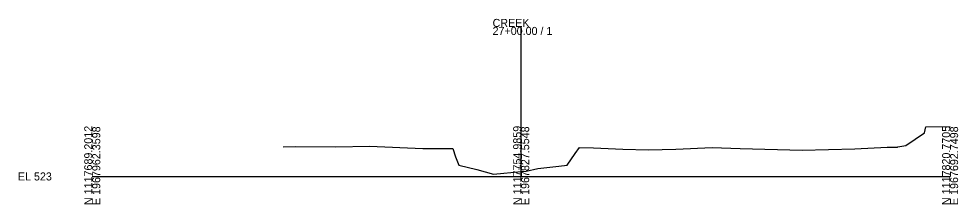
# Model space of a CAD drawing. Extents: x 9974 to 10303, y 9990 to 19550.
# Drawn here: x 9974.3 to 10302.8, y 16990.3 to 17055.1 of the extents above; entities that cross this region are included whole.
import ezdxf

# ---------------------------------------------------------------- set-up
doc = ezdxf.new("R2010")
doc.units = 0
for name, color, linetype in [('Level 10', 7, 'Continuous'), ('Level 60', 7, 'Continuous'), ('Level 63', 7, 'Continuous')]:
    doc.layers.add(name, color=color, linetype=linetype)

msp = doc.modelspace()

# ---------------------------------------------------------------- linework, layer by layer
at = {"layer": 'Level 60'}
for p, q in [((10284.54, 17010.84), (10291, 17015.18)), ((10291, 17015.18), (10291.56, 17017.33)), ((10291.56, 17017.33), (10299.98, 17017.41)), ((10299.98, 17017.41), (10300, 17017.41)), ((10066.8, 17010.4), (10071.23, 17010.43)), ((10071.23, 17010.43), (10085.16, 17010.39)), ((10085.16, 17010.39), (10097.01, 17010.6)), ((10097.01, 17010.6), (10115.59, 17009.72)), ((10115.59, 17009.72), (10126.08, 17009.73)), ((10126.08, 17009.73), (10127.07, 17006.86)), ((10168.84, 17007.98), (10170.4, 17010.15)), ((10170.4, 17010.15), (10175.27, 17009.97)), ((10175.27, 17009.97), (10185.52, 17009.58)), ((10185.52, 17009.58), (10194.51, 17009.27)), ((10194.51, 17009.27), (10204.12, 17009.58)), ((10204.12, 17009.58), (10216.77, 17010.13)), ((10216.77, 17010.13), (10226.55, 17009.75)), ((10226.55, 17009.75), (10248.22, 17009.19)), ((10248.22, 17009.19), (10266.69, 17009.59)), ((10266.69, 17009.59), (10277.98, 17010.28)), ((10277.98, 17010.28), (10280.03, 17010.23)), ((10280.03, 17010.23), (10281.63, 17010.22)), ((10281.63, 17010.22), (10281.69, 17010.38)), ((10281.69, 17010.38), (10284.54, 17010.84)), ((10127.07, 17006.86), (10128.19, 17003.9)), ((10166.09, 17003.99), (10168.84, 17007.98)), ((10128.19, 17003.9), (10134.48, 17002.37)), ((10134.48, 17002.37), (10140.32, 17000.77)), ((10140.32, 17000.77), (10150, 17001.72)), ((10150, 17001.72), (10151.79, 17001.9)), ((10151.79, 17001.9), (10155.87, 17002.74)), ((10155.87, 17002.74), (10163.19, 17003.57)), ((10163.19, 17003.57), (10166.09, 17003.99))]:
    msp.add_line(p, q, dxfattribs=at)
at = {"layer": 'Level 63'}
for p, q in [((10150, 17000), (10150, 17052.23)), ((10000, 17000), (10150, 17000)), ((10150, 17000), (10300, 17000))]:
    msp.add_line(p, q, dxfattribs=at)

# ---------------------------------------------------------------- texts
at = {"layer": 'Level 10'}
msp.add_text('524.720', height=0.8, rotation=90, dxfattribs=at).set_placement((10149.9, 17002.22))
at = {"layer": 'Level 63'}
for s, p in [('CREEK', (10140, 17052.23)), ('27+00.00 / 1', (10140, 17049.43)), ('EL 523', (9974, 16998.6))]:
    msp.add_text(s, height=2.8, dxfattribs=at).set_placement(p)
for s, p in [('N 1117689.2012', (10000, 16990)), ('E 1967962.3598', (10002.8, 16990)), ('N 1117754.9859', (10150, 16990)), ('E 1967827.5548', (10152.8, 16990)), ('N 1117820.7705', (10300, 16990)), ('E 1967692.7498', (10302.8, 16990))]:
    msp.add_text(s, height=2.8, rotation=90, dxfattribs=at).set_placement(p)

doc.saveas('drawing.dxf')
